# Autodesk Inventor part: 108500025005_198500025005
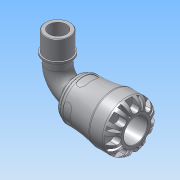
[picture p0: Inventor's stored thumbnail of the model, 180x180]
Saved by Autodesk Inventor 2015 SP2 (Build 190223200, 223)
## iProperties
Created: 2016-12
Part Number: 108500025005_198500025005
Material: PVC-Piping
Description: PLASSON 90° ELBOW WITH THREADED MALE OFFTAKE 25X1/2" SERIES 1
Document SubType Name: Modeling
Designer: KIM
Mass: 664.223 g
Surface Area: 733.008 cm^2
Volume: 474.445 cm^3
Density: 1.4 g/cm^3
Appearance: Smooth - White
Author: KIM
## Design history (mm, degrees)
derived "1085.ipt"
feature "Solid1::1085.ipt"
tag "TaggingFeature1"
body "Solid1"
other parameters: "d1" = 20.16, "d2" = 25, "d3" = 31.25, "d4" = 47, "d8" = 39.95, "d13" = 6.3, "d14" = 6.3, "d15" = 0, "d17" = 360 deg, "d19" = 8 deg, "d20" = 0.5, "d21" = 0.5, "d22" = 8 deg, "d24" = 0, "d26" = 360 deg, "d33" = 4.7, "d43" = 36.66, "d51" = 0.47, "d54" = 8.75, "d55" = 5.5, "d57" = 12.348, "d58" = 0, "d74" = 0, "d78" = 48, "d82" = 0.5, "d115" = 360 deg, "d207" = 90 deg, "d228" = 7.4375, "d247" = 0.94, "d248" = 2.88, "d268" = 21.9725, "d269" = 2.88, "d270" = 74, "d276" = 20.955, "d277" = 16, "d278" = 23.0505, "d279" = 44, "d280" = 17.6, "d281" = 3.14325, "d283" = 18.8595, "d286" = 0, "d287" = 0, "d288" = 14.6685, "d290" = 8.90025, "d292" = 30 deg, "d_" = 25, "E_" = 47, "l_" = 48, "A_" = 74, "A_1" = 44, "l_2" = 16, "R_" = 20.955, "d9" = 7.875, "d11" = 47, "d12" = 31.25, "d289" = 14.6685
